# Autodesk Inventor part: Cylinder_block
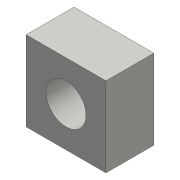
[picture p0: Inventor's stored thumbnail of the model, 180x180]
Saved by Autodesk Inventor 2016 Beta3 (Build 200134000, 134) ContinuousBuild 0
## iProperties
Created: 2016-03
Part Number: Cylinder_block
Material: Generic
Document SubType Name: Modeling
Designer: Gaurav
Density: 1 g/cm^3
Appearance: Default
Author: Gaurav
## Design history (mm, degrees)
sketch "Sketch1"
  geometry: L1 (25, 25)-(-25, 25); L2 (-25, 25)-(-25, -25); L3 (-25, -25)-(25, -25); L4 (25, -25)-(25, 25); L5 (25, 25)-(-25, -25); L6 (-25, 25)-(25, -25); C1 r 12.5 at (0, 0); 1 further point
  constraints: 12 end point, 2 midpoint, 2 parallel, 1 centre point, 1 coincident, 1 horizontal, 1 perpendicular
  dimensions: "d0" = 25 diameter of C1; "d1" = 50 distance of L3.end L2.end; "d2" = 50 distance of L2.end L1.end
extrude "Extrusion1" new body sketch "Sketch1" distance "d3" = 30; taper "d4" = 0 deg
body "Solid1"
